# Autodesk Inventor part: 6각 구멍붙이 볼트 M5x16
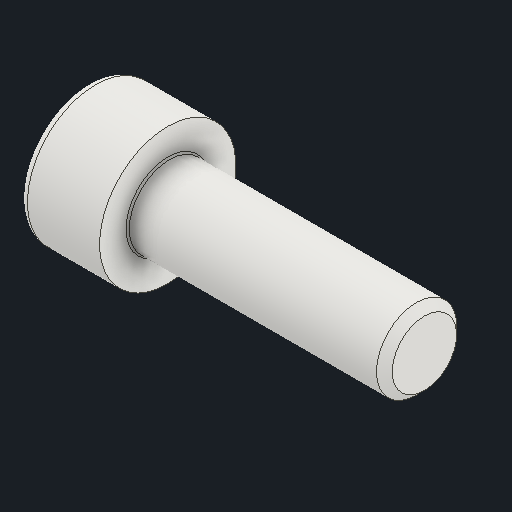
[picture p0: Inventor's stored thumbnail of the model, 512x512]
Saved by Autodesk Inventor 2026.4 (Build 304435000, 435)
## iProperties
Created: 2026-09
Part Number: 6각 구멍붙이 볼트 M5x16
Material: 강철, 연강
Description: 6각머리 태핑 나사
Document SubType Name: Modeling
Designer: user
Density: 7.85 g/cm^3
Appearance: 기본값
Author: jhkim
Sending System: Autodesk Inventor 2027
Preprocessor: ST-DEVELOPER v20.1
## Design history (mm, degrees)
feature "Solid1"
node "솔리드1"
